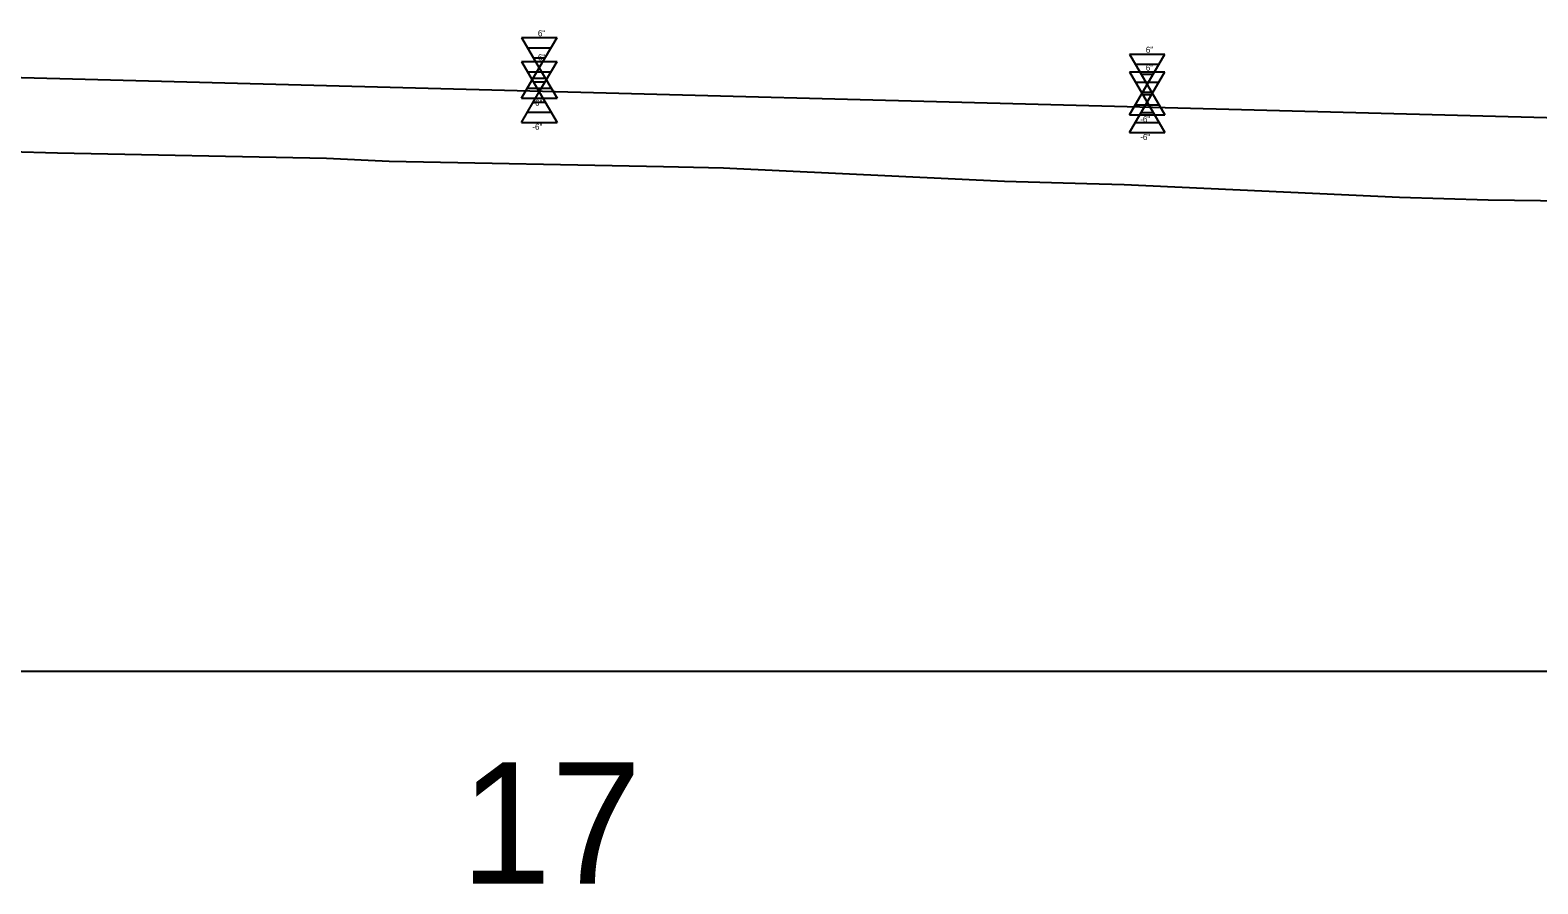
# Model space of a CAD drawing. Extents: x 573468 to 580768, y -57414 to -51768.
# Drawn here: x 574423.3 to 574547.3, y -53116 to -53045.8 of the extents above; entities that cross this region are included whole.
import ezdxf

# ---------------------------------------------------------------- set-up
doc = ezdxf.new("R2010")
doc.units = 0
for name, color, linetype in [('Exist Profile Cell', 7, 'Continuous'), ('Exist Vertical Profile Ground Line', 7, 'Continuous'), ('Exist Vertical Profile Horizontal Axis Label Major', 7, 'Continuous'), ('Pattern 2', 7, 'Continuous'), ('Prop Vertical Profile Grade', 7, 'Continuous'), ('Scratch_Level_0', 7, 'Continuous')]:
    doc.layers.add(name, color=color, linetype=linetype)

msp = doc.modelspace()

# ---------------------------------------------------------------- linework, layer by layer
at = {"layer": 'Exist Profile Cell'}
msp.add_line((573765.21, -53098.54), (577467.91, -53098.54), dxfattribs=at)
at = {"layer": 'Exist Vertical Profile Ground Line'}
msp.add_lwpolyline([(574292.82, -53053.4), (574315.41, -53052.98), (574322.97, -53053.21), (574343, -53053.82), (574348.87, -53053.96), (574353.25, -53054.08), (574375.55, -53054.77), (574380.65, -53054.9), (574387.91, -53055.04), (574394.84, -53055.23), (574417.09, -53055.67), (574417.72, -53055.69), (574425.6, -53055.91), (574447.7, -53056.35), (574452.88, -53056.58), (574475.44, -53057.03), (574480.38, -53057.13), (574480.89, -53057.16), (574503.48, -53058.22), (574510.26, -53058.41), (574513.31, -53058.5), (574535.96, -53059.56), (574543.26, -53059.77), (574554.03, -53059.91)], dxfattribs=at)
at = {"layer": 'Pattern 2'}
for p, q in [((574463.75, -53048.39), (574466.68, -53048.39)), ((574463.75, -53048.39), (574465.21, -53050.89)), ((574465.21, -53050.89), (574466.68, -53048.39)), ((574464.24, -53049.23), (574466.19, -53049.23)), ((574464.73, -53050.06), (574465.7, -53050.06)), ((574513.75, -53049.24), (574516.68, -53049.24)), ((574513.75, -53049.24), (574515.21, -53051.74)), ((574515.21, -53051.74), (574516.68, -53049.24)), ((574463.75, -53053.39), (574465.21, -53050.89)), ((574465.21, -53050.89), (574466.68, -53053.39)), ((574514.24, -53050.08), (574516.19, -53050.08)), ((574514.73, -53050.91), (574515.7, -53050.91)), ((574464.73, -53051.73), (574465.7, -53051.73)), ((574513.75, -53054.24), (574515.21, -53051.74)), ((574515.21, -53051.74), (574516.68, -53054.24)), ((574463.75, -53053.39), (574466.68, -53053.39)), ((574464.24, -53052.56), (574466.19, -53052.56)), ((574514.24, -53053.41), (574516.19, -53053.41)), ((574514.73, -53052.58), (574515.7, -53052.58)), ((574513.75, -53054.24), (574516.68, -53054.24))]:
    msp.add_line(p, q, dxfattribs=at)
at = {"layer": 'Prop Vertical Profile Grade'}
msp.add_line((574340.21, -53047.54), (574855.21, -53061.04), dxfattribs=at)
at = {"layer": 'Scratch_Level_0'}
for p, q in [((574463.75, -53046.41), (574466.68, -53046.41)), ((574463.75, -53046.41), (574465.21, -53048.91)), ((574464.24, -53047.25), (574466.19, -53047.25)), ((574465.21, -53048.91), (574466.68, -53046.41)), ((574464.73, -53048.08), (574465.7, -53048.08)), ((574513.75, -53047.77), (574516.68, -53047.77)), ((574513.75, -53047.77), (574515.21, -53050.27)), ((574514.24, -53048.61), (574516.19, -53048.61)), ((574515.21, -53050.27), (574516.68, -53047.77)), ((574463.75, -53051.41), (574465.21, -53048.91)), ((574464.73, -53049.75), (574465.7, -53049.75)), ((574465.21, -53048.91), (574466.68, -53051.41)), ((574514.73, -53049.44), (574515.7, -53049.44)), ((574464.24, -53050.58), (574466.19, -53050.58)), ((574513.75, -53052.77), (574515.21, -53050.27)), ((574514.73, -53051.11), (574515.7, -53051.11)), ((574515.21, -53050.27), (574516.68, -53052.77)), ((574463.75, -53051.41), (574466.68, -53051.41)), ((574514.24, -53051.94), (574516.19, -53051.94)), ((574513.75, -53052.77), (574516.68, -53052.77))]:
    msp.add_line(p, q, dxfattribs=at)

# ---------------------------------------------------------------- texts
at = {"layer": 'Exist Vertical Profile Horizontal Axis Label Major'}
msp.add_text('17', height=10, dxfattribs=at).set_placement((574458.75, -53116.04))
at = {"layer": 'Pattern 2'}
for s, p in [('6"', (574465.1, -53048.29)), ('6"', (574515.1, -53049.14)), ('-6"', (574464.64, -53054)), ('-6"', (574514.64, -53054.85))]:
    msp.add_text(s, height=0.5, rotation=360, dxfattribs=at).set_placement(p)
at = {"layer": 'Scratch_Level_0'}
for s, p in [('6"', (574465.1, -53046.31)), ('6"', (574515.1, -53047.67)), ('-6"', (574464.64, -53052.02)), ('-6"', (574514.64, -53053.38))]:
    msp.add_text(s, height=0.5, dxfattribs=at).set_placement(p)

doc.saveas('drawing.dxf')
